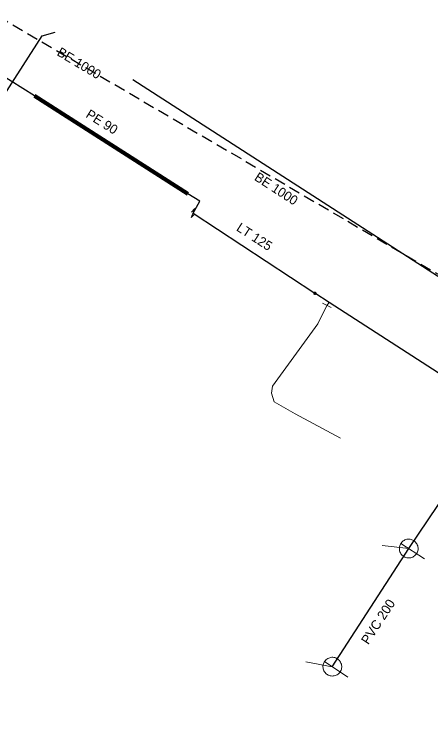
# Model space of a CAD drawing. Extents: x -791337 to -790755, y -988454 to -987923.
# Drawn here: x -791114.4 to -791070, y -988066.5 to -987990.3 of the extents above; entities that cross this region are included whole.
import ezdxf

# ---------------------------------------------------------------- set-up
doc = ezdxf.new("R2010")
doc.units = 0
doc.header["$LTSCALE"] = 0.4
doc.linetypes.add('MEDIUM_DASHED', pattern=[4.5, 3, -1.5])
for name, color, linetype, lineweight in [('1', 7, 'Continuous', 13), ('11', 7, 'Continuous', 13), ('13', 7, 'Continuous', 13), ('14', 7, 'Continuous', 25), ('17', 7, 'Continuous', 25), ('22', 7, 'Continuous', 13), ('3', 7, 'Continuous', 106), ('34', 7, 'Continuous', 13), ('47', 7, 'Continuous', 13), ('63', 7, 'MEDIUM_DASHED', 25), ('9', 7, 'Continuous', 13)]:
    doc.layers.add(name, color=color, linetype=linetype, lineweight=lineweight)

msp = doc.modelspace()

# ---------------------------------------------------------------- linework, layer by layer
at = {"layer": '11'}
for p, q in [((-791075.219, -988046.94), (-791072.379, -988047.249)), ((-791083.35, -988059.309), (-791080.519, -988059.839))]:
    msp.add_line(p, q, dxfattribs=at)
at = {"layer": '13'}
msp.add_lwpolyline([(-791081.107, -988021.33), (-791082.07, -988023.289), (-791086.879, -988029.96), (-791086.989, -988030.69), (-791086.71, -988031.629), (-791084.489, -988032.879), (-791079.636, -988035.487)], dxfattribs=at)
at = {"layer": '14'}
msp.add_line((-791101.789, -987997.26), (-791068, -988019.03), dxfattribs=at)
at = {"layer": '14', "lineweight": 13}
msp.add_line((-791080.872, -988021.03), (-791081.107, -988021.33), dxfattribs=at)
at = {"layer": '14'}
for points in [[(-791139.701, -988036.706), (-791111.445, -987992.605), (-791110.068, -987992.23)], [(-791080.519, -988059.839), (-791072.379, -988047.249), (-791064.19, -988035.129)]]:
    msp.add_lwpolyline(points, dxfattribs=at)
at = {"layer": '17'}
msp.add_line((-791095.362, -988011.495), (-791082.371, -988020.047), dxfattribs=at)
for points in [[(-791095.362, -988011.495), (-791094.625, -988010.232), (-791095.929, -988009.462), (-791112.248, -987998.984), (-791116.006, -987996.647), (-791116.776, -987997.707)], [(-791043.809, -988044.929), (-791080.872, -988021.03), (-791082.371, -988020.047)]]:
    msp.add_lwpolyline(points, dxfattribs=at)
at = {"layer": '22'}
for p, q in [((-791070.701, -988048.339), (-791073.217, -988046.704)), ((-791078.856, -988060.951), (-791081.349, -988059.282))]:
    msp.add_line(p, q, dxfattribs=at)
for points in [[(-791071.833, -988046.41), (-791071.928, -988046.356), (-791072.028, -988046.312), (-791072.133, -988046.28), (-791072.24, -988046.258), (-791072.35, -988046.249), (-791072.459, -988046.252), (-791072.568, -988046.267), (-791072.673, -988046.294), (-791072.777, -988046.331), (-791072.874, -988046.38), (-791072.966, -988046.44), (-791073.051, -988046.51), (-791073.128, -988046.587), (-791073.196, -988046.673), (-791073.254, -988046.767), (-791073.301, -988046.865), (-791073.338, -988046.968), (-791073.363, -988047.075), (-791073.376, -988047.184), (-791073.377, -988047.292), (-791073.366, -988047.402), (-791073.344, -988047.509), (-791073.309, -988047.613), (-791073.264, -988047.713), (-791073.208, -988047.807), (-791073.142, -988047.894), (-791073.066, -988047.974), (-791072.983, -988048.044), (-791072.892, -988048.106), (-791072.795, -988048.157), (-791072.694, -988048.198), (-791072.589, -988048.226), (-791072.481, -988048.244), (-791072.371, -988048.249), (-791072.261, -988048.242), (-791072.154, -988048.223), (-791072.048, -988048.193), (-791071.947, -988048.151), (-791071.851, -988048.099), (-791071.761, -988048.036), (-791071.679, -988047.964), (-791071.605, -988047.883), (-791071.54, -988047.795), (-791071.486, -988047.7), (-791071.442, -988047.599), (-791071.409, -988047.496), (-791071.388, -988047.388), (-791071.379, -988047.278), (-791071.382, -988047.169), (-791071.396, -988047.061), (-791071.422, -988046.954), (-791071.46, -988046.852), (-791071.509, -988046.753), (-791071.569, -988046.662), (-791071.637, -988046.577), (-791071.716, -988046.5), (-791071.802, -988046.432)], [(-791079.962, -988059.008), (-791080.056, -988058.952), (-791080.155, -988058.907), (-791080.26, -988058.873), (-791080.366, -988058.85), (-791080.476, -988058.839), (-791080.585, -988058.841), (-791080.694, -988058.854), (-791080.8, -988058.88), (-791080.904, -988058.916), (-791081.002, -988058.964), (-791081.095, -988059.022), (-791081.181, -988059.091), (-791081.259, -988059.167), (-791081.328, -988059.252), (-791081.387, -988059.345), (-791081.436, -988059.442), (-791081.474, -988059.545), (-791081.501, -988059.651), (-791081.515, -988059.76), (-791081.518, -988059.869), (-791081.508, -988059.979), (-791081.487, -988060.085), (-791081.454, -988060.191), (-791081.41, -988060.291), (-791081.356, -988060.385), (-791081.291, -988060.473), (-791081.216, -988060.554), (-791081.134, -988060.626), (-791081.044, -988060.689), (-791080.948, -988060.741), (-791080.847, -988060.783), (-791080.742, -988060.813), (-791080.634, -988060.832), (-791080.525, -988060.839), (-791080.415, -988060.833), (-791080.307, -988060.816), (-791080.201, -988060.787), (-791080.1, -988060.747), (-791080.003, -988060.696), (-791079.912, -988060.634), (-791079.829, -988060.564), (-791079.754, -988060.484), (-791079.688, -988060.396), (-791079.632, -988060.302), (-791079.587, -988060.202), (-791079.553, -988060.099), (-791079.53, -988059.991), (-791079.519, -988059.882), (-791079.521, -988059.773), (-791079.533, -988059.664), (-791079.558, -988059.557), (-791079.595, -988059.454), (-791079.642, -988059.355), (-791079.701, -988059.263), (-791079.768, -988059.177), (-791079.846, -988059.099), (-791079.931, -988059.03)]]:
    msp.add_lwpolyline(points, close=True, dxfattribs=at)
at = {"layer": '3'}
msp.add_line((-791112.248, -987998.985), (-791095.929, -988009.462), dxfattribs=at)
at = {"layer": '3', "lineweight": 100}
msp.add_line((-791112.248, -987998.985), (-791095.929, -988009.462), dxfattribs=at)
at = {"layer": '34'}
msp.add_line((-791081.555, -988021.109), (-791080.658, -988021.551), dxfattribs=at)
at = {"layer": '47'}
msp.add_line((-791095.168, -988011.023), (-791095.529, -988011.384), dxfattribs=at)
msp.add_lwpolyline([(-791095.168, -988011.023), (-791095.555, -988011.966), (-791095.194, -988011.605)], dxfattribs=at)
at = {"layer": '63'}
msp.add_lwpolyline([(-791231.02, -987923.132), (-790755.118, -988202.253), (-790755.118, -988202.253), (-790903.053, -988400.429), (-790903.053, -988400.429), (-791331.504, -988073.857), (-791331.504, -988073.857)], close=True, dxfattribs=at)
at = {"layer": '9'}
for points in [[(-791082.497, -988020.047), (-791082.497, -988020.06), (-791082.495, -988020.073), (-791082.492, -988020.086), (-791082.487, -988020.098), (-791082.481, -988020.11), (-791082.474, -988020.121), (-791082.466, -988020.131), (-791082.456, -988020.141), (-791082.446, -988020.149), (-791082.435, -988020.156), (-791082.423, -988020.162), (-791082.411, -988020.167), (-791082.398, -988020.17), (-791082.385, -988020.172), (-791082.372, -988020.174), (-791082.359, -988020.173), (-791082.346, -988020.171), (-791082.333, -988020.168), (-791082.321, -988020.163), (-791082.309, -988020.157), (-791082.298, -988020.15), (-791082.288, -988020.142), (-791082.278, -988020.132), (-791082.27, -988020.122), (-791082.263, -988020.111), (-791082.257, -988020.099), (-791082.252, -988020.087), (-791082.249, -988020.074), (-791082.247, -988020.061), (-791082.245, -988020.048), (-791082.246, -988020.035), (-791082.248, -988020.022), (-791082.251, -988020.009), (-791082.256, -988019.997), (-791082.262, -988019.985), (-791082.269, -988019.974), (-791082.277, -988019.964), (-791082.287, -988019.954), (-791082.297, -988019.946), (-791082.308, -988019.939), (-791082.32, -988019.933), (-791082.332, -988019.928), (-791082.345, -988019.925), (-791082.358, -988019.923), (-791082.371, -988019.922), (-791082.384, -988019.922), (-791082.397, -988019.924), (-791082.41, -988019.927), (-791082.422, -988019.932), (-791082.434, -988019.938), (-791082.445, -988019.945), (-791082.455, -988019.953), (-791082.465, -988019.963), (-791082.473, -988019.973), (-791082.48, -988019.984), (-791082.486, -988019.996), (-791082.491, -988020.008), (-791082.494, -988020.021), (-791082.496, -988020.034)], [(-791082.477, -988020.047), (-791082.478, -988020.058), (-791082.476, -988020.069), (-791082.473, -988020.08), (-791082.469, -988020.09), (-791082.464, -988020.1), (-791082.458, -988020.109), (-791082.451, -988020.118), (-791082.443, -988020.126), (-791082.434, -988020.133), (-791082.425, -988020.139), (-791082.415, -988020.144), (-791082.405, -988020.148), (-791082.394, -988020.151), (-791082.383, -988020.154), (-791082.372, -988020.154), (-791082.361, -988020.154), (-791082.35, -988020.152), (-791082.339, -988020.149), (-791082.329, -988020.145), (-791082.319, -988020.14), (-791082.31, -988020.134), (-791082.301, -988020.127), (-791082.293, -988020.119), (-791082.286, -988020.11), (-791082.28, -988020.101), (-791082.275, -988020.091), (-791082.271, -988020.081), (-791082.268, -988020.07), (-791082.266, -988020.059), (-791082.265, -988020.048), (-791082.265, -988020.037), (-791082.267, -988020.026), (-791082.27, -988020.015), (-791082.274, -988020.005), (-791082.279, -988019.995), (-791082.285, -988019.986), (-791082.292, -988019.977), (-791082.3, -988019.969), (-791082.309, -988019.962), (-791082.318, -988019.956), (-791082.328, -988019.951), (-791082.338, -988019.947), (-791082.349, -988019.944), (-791082.36, -988019.942), (-791082.371, -988019.942), (-791082.382, -988019.941), (-791082.393, -988019.943), (-791082.404, -988019.946), (-791082.414, -988019.95), (-791082.424, -988019.955), (-791082.433, -988019.961), (-791082.442, -988019.968), (-791082.45, -988019.976), (-791082.457, -988019.985), (-791082.463, -988019.994), (-791082.468, -988020.004), (-791082.472, -988020.014), (-791082.475, -988020.025), (-791082.477, -988020.036)], [(-791082.458, -988020.047), (-791082.458, -988020.056), (-791082.457, -988020.065), (-791082.454, -988020.074), (-791082.451, -988020.082), (-791082.447, -988020.09), (-791082.442, -988020.098), (-791082.436, -988020.105), (-791082.43, -988020.111), (-791082.423, -988020.117), (-791082.415, -988020.122), (-791082.407, -988020.126), (-791082.399, -988020.129), (-791082.39, -988020.132), (-791082.381, -988020.133), (-791082.372, -988020.135), (-791082.363, -988020.134), (-791082.354, -988020.133), (-791082.345, -988020.13), (-791082.337, -988020.127), (-791082.329, -988020.123), (-791082.321, -988020.118), (-791082.314, -988020.112), (-791082.308, -988020.106), (-791082.302, -988020.099), (-791082.297, -988020.091), (-791082.293, -988020.083), (-791082.29, -988020.075), (-791082.287, -988020.066), (-791082.286, -988020.057), (-791082.284, -988020.048), (-791082.285, -988020.039), (-791082.286, -988020.03), (-791082.289, -988020.021), (-791082.292, -988020.013), (-791082.296, -988020.005), (-791082.301, -988019.997), (-791082.307, -988019.99), (-791082.313, -988019.984), (-791082.32, -988019.978), (-791082.328, -988019.973), (-791082.336, -988019.969), (-791082.344, -988019.966), (-791082.353, -988019.963), (-791082.362, -988019.962), (-791082.371, -988019.961), (-791082.38, -988019.961), (-791082.389, -988019.962), (-791082.398, -988019.965), (-791082.406, -988019.968), (-791082.414, -988019.972), (-791082.422, -988019.977), (-791082.429, -988019.983), (-791082.435, -988019.989), (-791082.441, -988019.996), (-791082.446, -988020.004), (-791082.45, -988020.012), (-791082.453, -988020.02), (-791082.456, -988020.029), (-791082.457, -988020.038)], [(-791082.438, -988020.047), (-791082.438, -988020.054), (-791082.437, -988020.061), (-791082.436, -988020.068), (-791082.433, -988020.074), (-791082.43, -988020.08), (-791082.426, -988020.086), (-791082.422, -988020.092), (-791082.417, -988020.097), (-791082.411, -988020.101), (-791082.405, -988020.105), (-791082.399, -988020.108), (-791082.393, -988020.111), (-791082.386, -988020.112), (-791082.379, -988020.115), (-791082.372, -988020.115), (-791082.365, -988020.115), (-791082.358, -988020.113), (-791082.351, -988020.112), (-791082.345, -988020.109), (-791082.338, -988020.106), (-791082.333, -988020.102), (-791082.327, -988020.098), (-791082.322, -988020.093), (-791082.318, -988020.087), (-791082.314, -988020.081), (-791082.311, -988020.075), (-791082.308, -988020.069), (-791082.306, -988020.062), (-791082.305, -988020.055), (-791082.304, -988020.048), (-791082.304, -988020.041), (-791082.305, -988020.034), (-791082.307, -988020.027), (-791082.31, -988020.021), (-791082.313, -988020.014), (-791082.317, -988020.009), (-791082.321, -988020.003), (-791082.326, -988019.998), (-791082.332, -988019.994), (-791082.337, -988019.99), (-791082.344, -988019.987), (-791082.35, -988019.984), (-791082.357, -988019.982), (-791082.364, -988019.981), (-791082.371, -988019.981), (-791082.378, -988019.981), (-791082.385, -988019.981), (-791082.392, -988019.983), (-791082.398, -988019.986), (-791082.404, -988019.989), (-791082.41, -988019.993), (-791082.416, -988019.997), (-791082.421, -988020.002), (-791082.425, -988020.008), (-791082.429, -988020.013), (-791082.432, -988020.02), (-791082.435, -988020.026), (-791082.436, -988020.033), (-791082.438, -988020.04)], [(-791082.418, -988020.047), (-791082.418, -988020.052), (-791082.418, -988020.057), (-791082.417, -988020.062), (-791082.415, -988020.066), (-791082.413, -988020.071), (-791082.41, -988020.075), (-791082.407, -988020.078), (-791082.403, -988020.082), (-791082.4, -988020.085), (-791082.396, -988020.088), (-791082.391, -988020.09), (-791082.387, -988020.092), (-791082.382, -988020.093), (-791082.377, -988020.095), (-791082.372, -988020.095), (-791082.367, -988020.095), (-791082.362, -988020.094), (-791082.357, -988020.093), (-791082.353, -988020.091), (-791082.348, -988020.089), (-791082.344, -988020.086), (-791082.34, -988020.083), (-791082.337, -988020.079), (-791082.334, -988020.076), (-791082.331, -988020.072), (-791082.329, -988020.067), (-791082.327, -988020.063), (-791082.326, -988020.058), (-791082.325, -988020.053), (-791082.324, -988020.048), (-791082.324, -988020.043), (-791082.325, -988020.038), (-791082.326, -988020.033), (-791082.328, -988020.029), (-791082.33, -988020.024), (-791082.333, -988020.02), (-791082.336, -988020.016), (-791082.339, -988020.013), (-791082.343, -988020.01), (-791082.347, -988020.007), (-791082.352, -988020.005), (-791082.356, -988020.003), (-791082.361, -988020.002), (-791082.366, -988020.001), (-791082.371, -988020.001), (-791082.376, -988020.001), (-791082.381, -988020.002), (-791082.386, -988020.002), (-791082.39, -988020.004), (-791082.395, -988020.006), (-791082.399, -988020.009), (-791082.402, -988020.012), (-791082.406, -988020.015), (-791082.409, -988020.019), (-791082.412, -988020.023), (-791082.414, -988020.028), (-791082.416, -988020.032), (-791082.417, -988020.037), (-791082.418, -988020.042)], [(-791082.398, -988020.047), (-791082.398, -988020.05), (-791082.399, -988020.053), (-791082.398, -988020.055), (-791082.397, -988020.058), (-791082.396, -988020.061), (-791082.394, -988020.063), (-791082.392, -988020.065), (-791082.39, -988020.067), (-791082.388, -988020.069), (-791082.386, -988020.071), (-791082.383, -988020.073), (-791082.38, -988020.074), (-791082.378, -988020.074), (-791082.375, -988020.075), (-791082.372, -988020.075), (-791082.369, -988020.075), (-791082.366, -988020.075), (-791082.363, -988020.074), (-791082.361, -988020.073), (-791082.358, -988020.072), (-791082.356, -988020.07), (-791082.353, -988020.068), (-791082.351, -988020.066), (-791082.35, -988020.064), (-791082.348, -988020.062), (-791082.347, -988020.059), (-791082.345, -988020.056), (-791082.345, -988020.054), (-791082.344, -988020.051), (-791082.343, -988020.048), (-791082.344, -988020.045), (-791082.344, -988020.042), (-791082.345, -988020.039), (-791082.346, -988020.037), (-791082.347, -988020.034), (-791082.349, -988020.032), (-791082.35, -988020.029), (-791082.352, -988020.027), (-791082.355, -988020.026), (-791082.357, -988020.024), (-791082.36, -988020.023), (-791082.362, -988020.022), (-791082.365, -988020.021), (-791082.368, -988020.021), (-791082.371, -988020.02), (-791082.374, -988020.021), (-791082.377, -988020.02), (-791082.379, -988020.022), (-791082.382, -988020.022), (-791082.385, -988020.023), (-791082.387, -988020.025), (-791082.389, -988020.026), (-791082.391, -988020.028), (-791082.393, -988020.031), (-791082.395, -988020.033), (-791082.396, -988020.036), (-791082.397, -988020.038), (-791082.398, -988020.041), (-791082.398, -988020.044)], [(-791082.379, -988020.047), (-791082.379, -988020.049), (-791082.379, -988020.049), (-791082.378, -988020.049), (-791082.378, -988020.051), (-791082.379, -988020.052), (-791082.377, -988020.052), (-791082.377, -988020.052), (-791082.377, -988020.054), (-791082.377, -988020.054), (-791082.376, -988020.055), (-791082.374, -988020.055), (-791082.374, -988020.055), (-791082.374, -988020.056), (-791082.372, -988020.056), (-791082.372, -988020.056), (-791082.371, -988020.056), (-791082.37, -988020.056), (-791082.37, -988020.055), (-791082.369, -988020.055), (-791082.367, -988020.055), (-791082.367, -988020.054), (-791082.367, -988020.054), (-791082.366, -988020.053), (-791082.366, -988020.053), (-791082.364, -988020.052), (-791082.364, -988020.051), (-791082.363, -988020.05), (-791082.363, -988020.05), (-791082.363, -988020.049), (-791082.363, -988020.048), (-791082.363, -988020.047), (-791082.363, -988020.046), (-791082.363, -988020.046), (-791082.364, -988020.045), (-791082.364, -988020.044), (-791082.365, -988020.043), (-791082.365, -988020.043), (-791082.366, -988020.042), (-791082.366, -988020.042), (-791082.367, -988020.041), (-791082.368, -988020.041), (-791082.369, -988020.04), (-791082.369, -988020.04), (-791082.37, -988020.04), (-791082.371, -988020.04), (-791082.372, -988020.04), (-791082.373, -988020.04), (-791082.373, -988020.04), (-791082.374, -988020.041), (-791082.375, -988020.04), (-791082.376, -988020.042), (-791082.376, -988020.042), (-791082.377, -988020.042), (-791082.377, -988020.042), (-791082.378, -988020.044), (-791082.378, -988020.045), (-791082.378, -988020.046), (-791082.379, -988020.046), (-791082.379, -988020.047)]]:
    msp.add_lwpolyline(points, close=True, dxfattribs=at)

# ---------------------------------------------------------------- texts
at = {"layer": '1'}
for s, rotation, p in [('BE 1000 ', 329, (-791109.95, -987994.624)), ('PE 90 ', 328, (-791106.874, -988001.231)), ('BE 1000 ', 327, (-791088.912, -988007.917)), ('LT 125', 327, (-791090.83, -988013.299)), ('PVC 200 ', 57, (-791076.682, -988057.56))]:
    msp.add_text(s, height=1, rotation=rotation, dxfattribs=at).set_placement(p)

doc.saveas('drawing.dxf')
